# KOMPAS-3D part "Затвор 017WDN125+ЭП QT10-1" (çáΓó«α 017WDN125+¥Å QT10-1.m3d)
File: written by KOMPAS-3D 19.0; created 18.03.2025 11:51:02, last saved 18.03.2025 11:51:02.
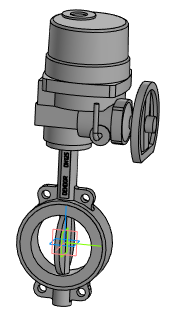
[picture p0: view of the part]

Document properties: Полное имя файла: Затвор 017WDN125+ЭП QT10-1.a3d

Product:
- Part/product: Затвор 017WDN125+ЭП QT10-1
    Масса: 49.6489

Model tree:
1. Операция без истории:1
